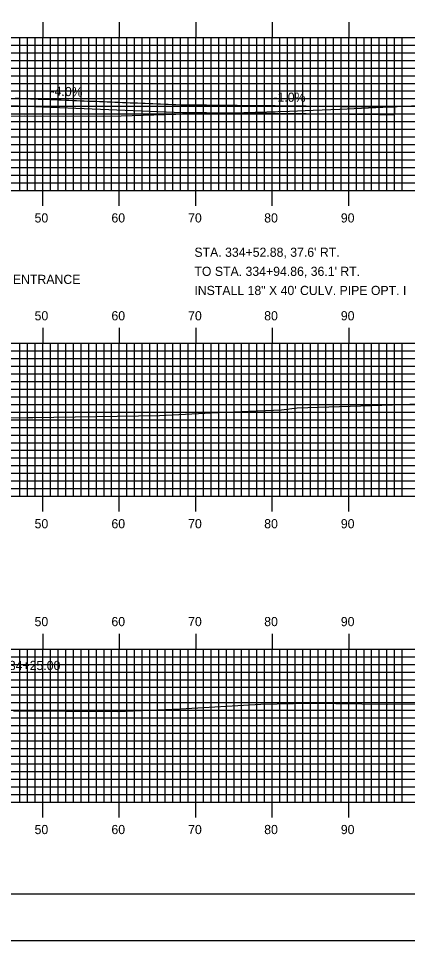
# Model space of a CAD drawing. Extents: x 1823179 to 1823522, y 442591 to 442811.
# Drawn here: x 1823391.6 to 1823442.5, y 442590.5 to 442711.2 of the extents above; entities that cross this region are included whole.
import ezdxf

# ---------------------------------------------------------------- set-up
doc = ezdxf.new("R2010")
doc.units = 0
for name, color, linetype in [('ANNOTATION', 7, 'Continuous'), ('BORDER', 7, 'Continuous'), ('D_Drainage_Text', 7, 'Continuous'), ('D_Roadway_Centerline', 7, 'Continuous'), ('D_Roadway_Drive_SubGrade', 7, 'Continuous'), ('D_Text_Standard', 7, 'Continuous'), ('H_V ANNOTATION', 7, 'Continuous'), ('MAJOR', 7, 'Continuous'), ('MINOR', 7, 'Continuous'), ('PLOT BOUNDARY', 7, 'Continuous'), ('S_Roadway_Centerline', 7, 'Continuous')]:
    doc.layers.add(name, color=color, linetype=linetype)

msp = doc.modelspace()

# ---------------------------------------------------------------- linework, layer by layer
at = {"layer": 'BORDER'}
msp.add_lwpolyline([(1823195.2, 442596.67), (1823515.2, 442596.67), (1823515.2, 442806.67), (1823195.2, 442806.67)], close=True, dxfattribs=at)
at = {"layer": 'D_Roadway_Centerline'}
msp.add_lwpolyline([(1823391.2, 442700.74), (1823391.7, 442700.72), (1823392.2, 442700.7), (1823392.7, 442700.68), (1823393.2, 442700.66), (1823393.7, 442700.64), (1823394.2, 442700.62), (1823394.7, 442700.6), (1823395.2, 442700.58), (1823395.7, 442700.56), (1823396.2, 442700.54), (1823396.7, 442700.52), (1823397.2, 442700.5), (1823397.7, 442700.48), (1823398.2, 442700.46), (1823398.7, 442700.44), (1823399.2, 442700.42), (1823399.7, 442700.4), (1823400.2, 442700.38), (1823400.7, 442700.36), (1823401.2, 442700.34), (1823401.7, 442700.32), (1823402.2, 442700.3), (1823402.7, 442700.28), (1823403.2, 442700.26), (1823403.7, 442700.24), (1823404.2, 442700.22), (1823404.7, 442700.2), (1823405.2, 442700.18), (1823405.7, 442700.16), (1823406.2, 442700.14), (1823406.7, 442700.12), (1823407.2, 442700.1), (1823407.7, 442700.08), (1823408.2, 442700.06), (1823408.7, 442700.04), (1823409.2, 442700.02), (1823409.7, 442700), (1823410.2, 442699.98), (1823410.7, 442699.96), (1823411.2, 442699.94), (1823411.7, 442699.92), (1823412.2, 442699.9), (1823412.7, 442699.88), (1823413.09, 442699.87), (1823413.2, 442699.87), (1823413.54, 442699.86), (1823413.7, 442699.86), (1823414.2, 442699.86), (1823414.7, 442699.85), (1823414.7, 442699.85), (1823415.2, 442699.85), (1823415.2, 442699.85), (1823415.7, 442699.84), (1823415.7, 442699.84), (1823416.2, 442699.84), (1823416.2, 442699.84), (1823416.7, 442699.83), (1823416.7, 442699.83), (1823417.2, 442699.83), (1823417.2, 442699.83), (1823417.42, 442699.82), (1823417.42, 442699.82), (1823417.7, 442699.82), (1823417.7, 442699.82), (1823418.19, 442699.82), (1823418.2, 442699.82), (1823418.69, 442699.81), (1823418.7, 442699.81), (1823419.19, 442699.81), (1823419.2, 442699.81), (1823419.69, 442699.8), (1823419.7, 442699.8), (1823420.19, 442699.8), (1823420.2, 442699.8), (1823420.69, 442699.79), (1823420.7, 442699.79), (1823421.19, 442699.79), (1823421.2, 442699.79), (1823421.3, 442699.79), (1823421.3, 442699.79), (1823421.69, 442699.78), (1823421.7, 442699.78), (1823422.19, 442699.78), (1823422.2, 442699.78), (1823422.69, 442699.77), (1823422.7, 442699.77), (1823423.18, 442699.77), (1823423.2, 442699.77), (1823423.68, 442699.76), (1823423.7, 442699.76), (1823424.18, 442699.76), (1823424.2, 442699.76), (1823424.68, 442699.75), (1823424.7, 442699.75), (1823425.16, 442699.75), (1823425.19, 442699.75), (1823425.19, 442699.75), (1823425.2, 442699.75), (1823425.68, 442699.74), (1823425.7, 442699.74), (1823426.18, 442699.74), (1823426.2, 442699.74), (1823426.23, 442699.74), (1823426.71, 442699.73), (1823426.74, 442699.73), (1823427.21, 442699.73), (1823427.24, 442699.73), (1823427.71, 442699.72), (1823428.17, 442699.72), (1823428.21, 442699.72), (1823428.25, 442699.72), (1823428.71, 442699.71), (1823428.74, 442699.71), (1823429.07, 442699.71), (1823429.08, 442699.71), (1823429.21, 442699.71), (1823429.25, 442699.71), (1823429.71, 442699.7), (1823429.76, 442699.7), (1823430.21, 442699.7), (1823430.26, 442699.7), (1823430.72, 442699.69), (1823430.77, 442699.69), (1823431.22, 442699.69), (1823431.66, 442699.68), (1823431.72, 442699.68), (1823431.78, 442699.68), (1823432.22, 442699.68), (1823432.28, 442699.68), (1823432.72, 442699.67), (1823432.75, 442699.67), (1823432.97, 442699.67), (1823433.19, 442699.67), (1823433.23, 442699.67), (1823433.29, 442699.67), (1823433.73, 442699.66), (1823433.8, 442699.66), (1823434.23, 442699.66), (1823434.3, 442699.66), (1823434.73, 442699.65), (1823434.81, 442699.65), (1823435.23, 442699.65), (1823435.32, 442699.65), (1823435.74, 442699.64), (1823435.82, 442699.64), (1823436.24, 442699.64), (1823436.33, 442699.64), (1823436.74, 442699.63), (1823436.84, 442699.63), (1823436.86, 442699.63), (1823436.94, 442699.63), (1823437.25, 442699.63), (1823437.34, 442699.63), (1823437.75, 442699.62), (1823437.85, 442699.62), (1823438.25, 442699.62), (1823438.36, 442699.62), (1823438.76, 442699.61), (1823438.87, 442699.61), (1823439.26, 442699.61), (1823439.37, 442699.61), (1823439.76, 442699.6), (1823439.88, 442699.6), (1823440.27, 442699.6), (1823440.39, 442699.6), (1823440.77, 442699.59)], dxfattribs=at)
at = {"layer": 'D_Roadway_Drive_SubGrade'}
msp.add_line((1823440.77, 442699.59), (1823440.77, 442698.59), dxfattribs=at)
msp.add_lwpolyline([(1823382.99, 442700.07), (1823413.07, 442698.87), (1823414.69, 442698.85), (1823414.69, 442698.85), (1823415.19, 442698.85), (1823415.19, 442698.85), (1823415.69, 442698.84), (1823415.69, 442698.84), (1823416.19, 442698.84), (1823416.19, 442698.84), (1823416.69, 442698.83), (1823416.69, 442698.83), (1823417.19, 442698.83), (1823417.19, 442698.83), (1823417.41, 442698.82), (1823417.41, 442698.82), (1823417.69, 442698.82), (1823417.69, 442698.82), (1823418.18, 442698.82), (1823418.19, 442698.82), (1823418.68, 442698.81), (1823418.69, 442698.81), (1823419.18, 442698.81), (1823419.19, 442698.81), (1823419.68, 442698.8), (1823419.69, 442698.8), (1823420.18, 442698.8), (1823420.19, 442698.8), (1823420.68, 442698.79), (1823420.69, 442698.79), (1823421.18, 442698.79), (1823421.19, 442698.79), (1823421.29, 442698.79), (1823421.29, 442698.79), (1823421.68, 442698.78), (1823421.69, 442698.78), (1823422.18, 442698.78), (1823422.19, 442698.78), (1823422.68, 442698.77), (1823422.69, 442698.77), (1823423.17, 442698.77), (1823423.19, 442698.77), (1823423.67, 442698.76), (1823423.69, 442698.76), (1823424.17, 442698.76), (1823424.19, 442698.76), (1823424.67, 442698.75), (1823424.69, 442698.75), (1823425.15, 442698.75), (1823425.18, 442698.75), (1823425.67, 442698.74), (1823425.69, 442698.74), (1823426.17, 442698.74), (1823426.22, 442698.74), (1823426.7, 442698.73), (1823426.73, 442698.73), (1823427.2, 442698.73), (1823427.23, 442698.73), (1823428.16, 442698.72), (1823428.24, 442698.72), (1823428.7, 442698.71), (1823428.73, 442698.71), (1823429.06, 442698.71), (1823429.07, 442698.71), (1823429.2, 442698.71), (1823429.24, 442698.71), (1823429.7, 442698.7), (1823429.75, 442698.7), (1823430.2, 442698.7), (1823430.25, 442698.7), (1823430.71, 442698.69), (1823430.76, 442698.69), (1823431.65, 442698.68), (1823431.77, 442698.68), (1823432.21, 442698.68), (1823432.27, 442698.68), (1823432.71, 442698.67), (1823432.74, 442698.67), (1823433.18, 442698.67), (1823433.28, 442698.67), (1823433.72, 442698.66), (1823433.79, 442698.66), (1823434.22, 442698.66), (1823434.29, 442698.66), (1823434.72, 442698.65), (1823434.8, 442698.65), (1823435.23, 442698.65), (1823435.31, 442698.65), (1823435.73, 442698.64), (1823435.81, 442698.64), (1823436.23, 442698.64), (1823436.32, 442698.64), (1823436.83, 442698.63), (1823436.93, 442698.63), (1823437.24, 442698.63), (1823437.33, 442698.63), (1823437.74, 442698.62), (1823437.84, 442698.62), (1823438.24, 442698.62), (1823438.35, 442698.62), (1823438.75, 442698.61), (1823438.86, 442698.61), (1823439.25, 442698.61), (1823439.36, 442698.61), (1823439.75, 442698.6), (1823439.87, 442698.6), (1823440.26, 442698.6), (1823440.38, 442698.6), (1823440.77, 442698.59)], dxfattribs=at)
at = {"layer": 'MAJOR'}
for p, q in [((1823394.8, 442710.67), (1823394.8, 442708.67)), ((1823404.8, 442710.67), (1823404.8, 442708.67)), ((1823414.8, 442710.67), (1823414.8, 442708.67)), ((1823424.8, 442710.67), (1823424.8, 442708.67)), ((1823434.8, 442710.67), (1823434.8, 442708.67)), ((1823344.8, 442708.67), (1823484.8, 442708.67)), ((1823344.8, 442708.67), (1823484.8, 442708.67)), ((1823394.8, 442688.67), (1823394.8, 442708.67)), ((1823404.8, 442688.67), (1823404.8, 442708.67)), ((1823414.8, 442688.67), (1823414.8, 442708.67)), ((1823424.8, 442688.67), (1823424.8, 442708.67)), ((1823434.8, 442688.67), (1823434.8, 442708.67)), ((1823344.8, 442703.67), (1823484.8, 442703.67)), ((1823344.8, 442698.67), (1823484.8, 442698.67)), ((1823344.8, 442693.67), (1823484.8, 442693.67)), ((1823344.8, 442688.67), (1823484.8, 442688.67)), ((1823344.8, 442688.67), (1823484.8, 442688.67)), ((1823394.8, 442686.66), (1823394.8, 442688.67)), ((1823404.8, 442686.66), (1823404.8, 442688.67)), ((1823414.8, 442686.66), (1823414.8, 442688.67)), ((1823424.8, 442686.66), (1823424.8, 442688.67)), ((1823434.8, 442686.66), (1823434.8, 442688.67)), ((1823394.8, 442670.67), (1823394.8, 442668.67)), ((1823404.8, 442670.67), (1823404.8, 442668.67)), ((1823414.8, 442670.67), (1823414.8, 442668.67)), ((1823424.8, 442670.67), (1823424.8, 442668.67)), ((1823434.8, 442670.67), (1823434.8, 442668.67)), ((1823204.8, 442668.67), (1823484.8, 442668.67)), ((1823204.8, 442668.67), (1823484.8, 442668.67)), ((1823394.8, 442648.67), (1823394.8, 442668.67)), ((1823404.8, 442648.67), (1823404.8, 442668.67)), ((1823414.8, 442648.67), (1823414.8, 442668.67)), ((1823424.8, 442648.67), (1823424.8, 442668.67)), ((1823434.8, 442648.67), (1823434.8, 442668.67)), ((1823204.8, 442663.67), (1823484.8, 442663.67)), ((1823204.8, 442658.67), (1823484.8, 442658.67)), ((1823204.8, 442653.67), (1823484.8, 442653.67)), ((1823204.8, 442648.67), (1823484.8, 442648.67)), ((1823204.8, 442648.67), (1823484.8, 442648.67)), ((1823394.8, 442646.66), (1823394.8, 442648.67)), ((1823404.8, 442646.66), (1823404.8, 442648.67)), ((1823414.8, 442646.66), (1823414.8, 442648.67)), ((1823424.8, 442646.66), (1823424.8, 442648.67)), ((1823434.8, 442646.66), (1823434.8, 442648.67)), ((1823394.8, 442630.67), (1823394.8, 442628.67)), ((1823404.8, 442630.67), (1823404.8, 442628.67)), ((1823414.8, 442630.67), (1823414.8, 442628.67)), ((1823424.8, 442630.67), (1823424.8, 442628.67)), ((1823434.8, 442630.67), (1823434.8, 442628.67)), ((1823204.8, 442628.67), (1823484.8, 442628.67)), ((1823204.8, 442628.67), (1823484.8, 442628.67)), ((1823394.8, 442608.67), (1823394.8, 442628.67)), ((1823404.8, 442608.67), (1823404.8, 442628.67)), ((1823414.8, 442608.67), (1823414.8, 442628.67)), ((1823424.8, 442608.67), (1823424.8, 442628.67)), ((1823434.8, 442608.67), (1823434.8, 442628.67)), ((1823204.8, 442623.67), (1823484.8, 442623.67)), ((1823204.8, 442618.67), (1823484.8, 442618.67)), ((1823204.8, 442613.67), (1823484.8, 442613.67)), ((1823204.8, 442608.67), (1823484.8, 442608.67)), ((1823204.8, 442608.67), (1823484.8, 442608.67)), ((1823394.8, 442606.66), (1823394.8, 442608.67)), ((1823404.8, 442606.66), (1823404.8, 442608.67)), ((1823414.8, 442606.66), (1823414.8, 442608.67)), ((1823424.8, 442606.66), (1823424.8, 442608.67)), ((1823434.8, 442606.66), (1823434.8, 442608.67))]:
    msp.add_line(p, q, dxfattribs=at)
at = {"layer": 'MINOR'}
for p, q in [((1823391.8, 442688.67), (1823391.8, 442708.67)), ((1823392.8, 442688.67), (1823392.8, 442708.67)), ((1823393.8, 442688.67), (1823393.8, 442708.67)), ((1823395.8, 442688.67), (1823395.8, 442708.67)), ((1823396.8, 442688.67), (1823396.8, 442708.67)), ((1823397.8, 442688.67), (1823397.8, 442708.67)), ((1823398.8, 442688.67), (1823398.8, 442708.67)), ((1823399.8, 442688.67), (1823399.8, 442708.67)), ((1823400.8, 442688.67), (1823400.8, 442708.67)), ((1823401.8, 442688.67), (1823401.8, 442708.67)), ((1823402.8, 442688.67), (1823402.8, 442708.67)), ((1823403.8, 442688.67), (1823403.8, 442708.67)), ((1823405.8, 442688.67), (1823405.8, 442708.67)), ((1823406.8, 442688.67), (1823406.8, 442708.67)), ((1823407.8, 442688.67), (1823407.8, 442708.67)), ((1823408.8, 442688.67), (1823408.8, 442708.67)), ((1823409.8, 442688.67), (1823409.8, 442708.67)), ((1823410.8, 442688.67), (1823410.8, 442708.67)), ((1823411.8, 442688.67), (1823411.8, 442708.67)), ((1823412.8, 442688.67), (1823412.8, 442708.67)), ((1823413.8, 442688.67), (1823413.8, 442708.67)), ((1823415.8, 442688.67), (1823415.8, 442708.67)), ((1823416.8, 442688.67), (1823416.8, 442708.67)), ((1823417.8, 442688.67), (1823417.8, 442708.67)), ((1823418.8, 442688.67), (1823418.8, 442708.67)), ((1823419.8, 442688.67), (1823419.8, 442708.67)), ((1823420.8, 442688.67), (1823420.8, 442708.67)), ((1823421.8, 442688.67), (1823421.8, 442708.67)), ((1823422.8, 442688.67), (1823422.8, 442708.67)), ((1823423.8, 442688.67), (1823423.8, 442708.67)), ((1823425.8, 442688.67), (1823425.8, 442708.67)), ((1823426.8, 442688.67), (1823426.8, 442708.67)), ((1823427.8, 442688.67), (1823427.8, 442708.67)), ((1823428.8, 442688.67), (1823428.8, 442708.67)), ((1823429.8, 442688.67), (1823429.8, 442708.67)), ((1823430.8, 442688.67), (1823430.8, 442708.67)), ((1823431.8, 442688.67), (1823431.8, 442708.67)), ((1823432.8, 442688.67), (1823432.8, 442708.67)), ((1823433.8, 442688.67), (1823433.8, 442708.67)), ((1823435.8, 442688.67), (1823435.8, 442708.67)), ((1823436.8, 442688.67), (1823436.8, 442708.67)), ((1823437.8, 442688.67), (1823437.8, 442708.67)), ((1823438.8, 442688.67), (1823438.8, 442708.67)), ((1823439.8, 442688.67), (1823439.8, 442708.67)), ((1823440.8, 442688.67), (1823440.8, 442708.67)), ((1823441.8, 442688.67), (1823441.8, 442708.67)), ((1823344.8, 442707.67), (1823484.8, 442707.67)), ((1823344.8, 442706.67), (1823484.8, 442706.67)), ((1823344.8, 442705.67), (1823484.8, 442705.67)), ((1823344.8, 442704.67), (1823484.8, 442704.67)), ((1823344.8, 442702.67), (1823484.8, 442702.67)), ((1823344.8, 442701.67), (1823484.8, 442701.67)), ((1823344.8, 442700.67), (1823484.8, 442700.67)), ((1823344.8, 442699.67), (1823484.8, 442699.67)), ((1823344.8, 442697.67), (1823484.8, 442697.67)), ((1823344.8, 442696.67), (1823484.8, 442696.67)), ((1823344.8, 442695.67), (1823484.8, 442695.67)), ((1823344.8, 442694.67), (1823484.8, 442694.67)), ((1823344.8, 442692.67), (1823484.8, 442692.67)), ((1823344.8, 442691.67), (1823484.8, 442691.67)), ((1823344.8, 442690.67), (1823484.8, 442690.67)), ((1823344.8, 442689.67), (1823484.8, 442689.67)), ((1823391.8, 442648.67), (1823391.8, 442668.67)), ((1823392.8, 442648.67), (1823392.8, 442668.67)), ((1823393.8, 442648.67), (1823393.8, 442668.67)), ((1823395.8, 442648.67), (1823395.8, 442668.67)), ((1823396.8, 442648.67), (1823396.8, 442668.67)), ((1823397.8, 442648.67), (1823397.8, 442668.67)), ((1823398.8, 442648.67), (1823398.8, 442668.67)), ((1823399.8, 442648.67), (1823399.8, 442668.67)), ((1823400.8, 442648.67), (1823400.8, 442668.67)), ((1823401.8, 442648.67), (1823401.8, 442668.67)), ((1823402.8, 442648.67), (1823402.8, 442668.67)), ((1823403.8, 442648.67), (1823403.8, 442668.67)), ((1823405.8, 442648.67), (1823405.8, 442668.67)), ((1823406.8, 442648.67), (1823406.8, 442668.67)), ((1823407.8, 442648.67), (1823407.8, 442668.67)), ((1823408.8, 442648.67), (1823408.8, 442668.67)), ((1823409.8, 442648.67), (1823409.8, 442668.67)), ((1823410.8, 442648.67), (1823410.8, 442668.67)), ((1823411.8, 442648.67), (1823411.8, 442668.67)), ((1823412.8, 442648.67), (1823412.8, 442668.67)), ((1823413.8, 442648.67), (1823413.8, 442668.67)), ((1823415.8, 442648.67), (1823415.8, 442668.67)), ((1823416.8, 442648.67), (1823416.8, 442668.67)), ((1823417.8, 442648.67), (1823417.8, 442668.67)), ((1823418.8, 442648.67), (1823418.8, 442668.67)), ((1823419.8, 442648.67), (1823419.8, 442668.67)), ((1823420.8, 442648.67), (1823420.8, 442668.67)), ((1823421.8, 442648.67), (1823421.8, 442668.67)), ((1823422.8, 442648.67), (1823422.8, 442668.67)), ((1823423.8, 442648.67), (1823423.8, 442668.67)), ((1823425.8, 442648.67), (1823425.8, 442668.67)), ((1823426.8, 442648.67), (1823426.8, 442668.67)), ((1823427.8, 442648.67), (1823427.8, 442668.67)), ((1823428.8, 442648.67), (1823428.8, 442668.67)), ((1823429.8, 442648.67), (1823429.8, 442668.67)), ((1823430.8, 442648.67), (1823430.8, 442668.67)), ((1823431.8, 442648.67), (1823431.8, 442668.67)), ((1823432.8, 442648.67), (1823432.8, 442668.67)), ((1823433.8, 442648.67), (1823433.8, 442668.67)), ((1823435.8, 442648.67), (1823435.8, 442668.67)), ((1823436.8, 442648.67), (1823436.8, 442668.67)), ((1823437.8, 442648.67), (1823437.8, 442668.67)), ((1823438.8, 442648.67), (1823438.8, 442668.67)), ((1823439.8, 442648.67), (1823439.8, 442668.67)), ((1823440.8, 442648.67), (1823440.8, 442668.67)), ((1823441.8, 442648.67), (1823441.8, 442668.67)), ((1823204.8, 442667.67), (1823484.8, 442667.67)), ((1823204.8, 442666.67), (1823484.8, 442666.67)), ((1823204.8, 442665.67), (1823484.8, 442665.67)), ((1823204.8, 442664.67), (1823484.8, 442664.67)), ((1823204.8, 442662.67), (1823484.8, 442662.67)), ((1823204.8, 442661.67), (1823484.8, 442661.67)), ((1823204.8, 442660.67), (1823484.8, 442660.67)), ((1823204.8, 442659.67), (1823484.8, 442659.67)), ((1823204.8, 442657.67), (1823484.8, 442657.67)), ((1823204.8, 442656.67), (1823484.8, 442656.67)), ((1823204.8, 442655.67), (1823484.8, 442655.67)), ((1823204.8, 442654.67), (1823484.8, 442654.67)), ((1823204.8, 442652.67), (1823484.8, 442652.67)), ((1823204.8, 442651.67), (1823484.8, 442651.67)), ((1823204.8, 442650.67), (1823484.8, 442650.67)), ((1823204.8, 442649.67), (1823484.8, 442649.67)), ((1823391.8, 442608.67), (1823391.8, 442628.67)), ((1823392.8, 442608.67), (1823392.8, 442628.67)), ((1823393.8, 442608.67), (1823393.8, 442628.67)), ((1823395.8, 442608.67), (1823395.8, 442628.67)), ((1823396.8, 442608.67), (1823396.8, 442628.67)), ((1823397.8, 442608.67), (1823397.8, 442628.67)), ((1823398.8, 442608.67), (1823398.8, 442628.67)), ((1823399.8, 442608.67), (1823399.8, 442628.67)), ((1823400.8, 442608.67), (1823400.8, 442628.67)), ((1823401.8, 442608.67), (1823401.8, 442628.67)), ((1823402.8, 442608.67), (1823402.8, 442628.67)), ((1823403.8, 442608.67), (1823403.8, 442628.67)), ((1823405.8, 442608.67), (1823405.8, 442628.67)), ((1823406.8, 442608.67), (1823406.8, 442628.67)), ((1823407.8, 442608.67), (1823407.8, 442628.67)), ((1823408.8, 442608.67), (1823408.8, 442628.67)), ((1823409.8, 442608.67), (1823409.8, 442628.67)), ((1823410.8, 442608.67), (1823410.8, 442628.67)), ((1823411.8, 442608.67), (1823411.8, 442628.67)), ((1823412.8, 442608.67), (1823412.8, 442628.67)), ((1823413.8, 442608.67), (1823413.8, 442628.67)), ((1823415.8, 442608.67), (1823415.8, 442628.67)), ((1823416.8, 442608.67), (1823416.8, 442628.67)), ((1823417.8, 442608.67), (1823417.8, 442628.67)), ((1823418.8, 442608.67), (1823418.8, 442628.67)), ((1823419.8, 442608.67), (1823419.8, 442628.67)), ((1823420.8, 442608.67), (1823420.8, 442628.67)), ((1823421.8, 442608.67), (1823421.8, 442628.67)), ((1823422.8, 442608.67), (1823422.8, 442628.67)), ((1823423.8, 442608.67), (1823423.8, 442628.67)), ((1823425.8, 442608.67), (1823425.8, 442628.67)), ((1823426.8, 442608.67), (1823426.8, 442628.67)), ((1823427.8, 442608.67), (1823427.8, 442628.67)), ((1823428.8, 442608.67), (1823428.8, 442628.67)), ((1823429.8, 442608.67), (1823429.8, 442628.67)), ((1823430.8, 442608.67), (1823430.8, 442628.67)), ((1823431.8, 442608.67), (1823431.8, 442628.67)), ((1823432.8, 442608.67), (1823432.8, 442628.67)), ((1823433.8, 442608.67), (1823433.8, 442628.67)), ((1823435.8, 442608.67), (1823435.8, 442628.67)), ((1823436.8, 442608.67), (1823436.8, 442628.67)), ((1823437.8, 442608.67), (1823437.8, 442628.67)), ((1823438.8, 442608.67), (1823438.8, 442628.67)), ((1823439.8, 442608.67), (1823439.8, 442628.67)), ((1823440.8, 442608.67), (1823440.8, 442628.67)), ((1823441.8, 442608.67), (1823441.8, 442628.67)), ((1823204.8, 442627.67), (1823484.8, 442627.67)), ((1823204.8, 442626.67), (1823484.8, 442626.67)), ((1823204.8, 442625.67), (1823484.8, 442625.67)), ((1823204.8, 442624.67), (1823484.8, 442624.67)), ((1823204.8, 442622.67), (1823484.8, 442622.67)), ((1823204.8, 442621.67), (1823484.8, 442621.67)), ((1823204.8, 442620.67), (1823484.8, 442620.67)), ((1823204.8, 442619.67), (1823484.8, 442619.67)), ((1823204.8, 442617.67), (1823484.8, 442617.67)), ((1823204.8, 442616.67), (1823484.8, 442616.67)), ((1823204.8, 442615.67), (1823484.8, 442615.67)), ((1823204.8, 442614.67), (1823484.8, 442614.67)), ((1823204.8, 442612.67), (1823484.8, 442612.67)), ((1823204.8, 442611.67), (1823484.8, 442611.67)), ((1823204.8, 442610.67), (1823484.8, 442610.67)), ((1823204.8, 442609.67), (1823484.8, 442609.67))]:
    msp.add_line(p, q, dxfattribs=at)
at = {"layer": 'PLOT BOUNDARY'}
msp.add_lwpolyline([(1823179.01, 442590.55), (1823519.01, 442590.55), (1823519.01, 442810.55), (1823179.01, 442810.55)], close=True, dxfattribs=at)
at = {"layer": 'S_Roadway_Centerline'}
for points in [[(1823344.8, 442698.01), (1823348.35, 442697.93), (1823351.37, 442697.74), (1823358.06, 442697.86), (1823362.21, 442697.71), (1823369.44, 442697.79), (1823371.44, 442698.06), (1823379.29, 442698.14), (1823392.39, 442698.41), (1823402.68, 442698.38), (1823405.05, 442698.41), (1823413.61, 442698.69), (1823421.09, 442698.84), (1823427.05, 442699.05), (1823430.17, 442699.15), (1823433.66, 442699.28), (1823443.96, 442699.75)], [(1823378.53, 442658.94), (1823392.78, 442658.97), (1823392.92, 442658.97), (1823393.5, 442658.96), (1823410.04, 442659.23), (1823417.68, 442659.6), (1823425.99, 442659.96), (1823428.08, 442660.24), (1823441.92, 442660.68), (1823444.54, 442660.79)], [(1823390.96, 442620.58), (1823404.58, 442620.5), (1823412.82, 442620.86), (1823423.3, 442621.47), (1823429.72, 442621.61), (1823439.9, 442621.48), (1823443.68, 442621.53)]]:
    msp.add_lwpolyline(points, dxfattribs=at)

# ---------------------------------------------------------------- texts
at = {"layer": 'ANNOTATION'}
for s, rotation, p in [('-4.0%', 357.7094, (1823395.79, 442701.09)), ('-1.0%', 359.4286, (1823424.95, 442700.28))]:
    msp.add_text(s, height=1.2, rotation=rotation, dxfattribs=at).set_placement(p)
at = {"layer": 'D_Drainage_Text'}
msp.add_text('STA. 334+25.00', height=1.2, dxfattribs=at).set_placement((1823385.45, 442625.93))
at = {"layer": 'D_Text_Standard'}
for s, p in [("STA. 334+52.88, 37.6' RT.", (1823414.62, 442679.98)), ("TO STA. 334+94.86, 36.1' RT.", (1823414.62, 442677.48)), ('CONSTRUCT PAVED ENTRANCE', (1823374.48, 442676.43)), ('INSTALL 18" X 40\' CULV. PIPE OPT. I', (1823414.62, 442674.98))]:
    msp.add_text(s, height=1.2, dxfattribs=at).set_placement(p)
at = {"layer": 'H_V ANNOTATION'}
for s, p in [('50', (1823393.72, 442684.47)), ('60', (1823403.77, 442684.47)), ('70', (1823413.8, 442684.47)), ('80', (1823423.75, 442684.47)), ('90', (1823433.77, 442684.47)), ('50', (1823393.72, 442671.67)), ('60', (1823403.77, 442671.67)), ('70', (1823413.8, 442671.67)), ('80', (1823423.75, 442671.67)), ('90', (1823433.77, 442671.67)), ('50', (1823393.72, 442644.47)), ('60', (1823403.77, 442644.47)), ('70', (1823413.8, 442644.47)), ('80', (1823423.75, 442644.47)), ('90', (1823433.77, 442644.47)), ('50', (1823393.72, 442631.67)), ('60', (1823403.77, 442631.67)), ('70', (1823413.8, 442631.67)), ('80', (1823423.75, 442631.67)), ('90', (1823433.77, 442631.67)), ('50', (1823393.72, 442604.47)), ('60', (1823403.77, 442604.47)), ('70', (1823413.8, 442604.47)), ('80', (1823423.75, 442604.47)), ('90', (1823433.77, 442604.47))]:
    msp.add_text(s, height=1.2, dxfattribs=at).set_placement(p)

doc.saveas('drawing.dxf')
